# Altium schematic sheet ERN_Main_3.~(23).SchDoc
size A; SheetNumber: 3; SheetTotal: 3; SPICEModelCacheXVWYUVSQ: <root> / <DocumentId>XVWYUVSQ</DocumentId> / <CacheFrame Number="0"> / <Model Name="irf1010" Kind="CKT"> / <Text>*IRF1010 MCE 4-2-96 / *55V  75A .014 ohm HEXFET pkg:TO-220 2,1,3 / .SUBCKT IRF1010  10 20 40 40 / M1   1  2  3  3  DMOS L=1U W=1U / RD  10  1  5.65M / RS  30  3  1.35M / RG  20  2  12.1 / CGS  2  3  2.15N / EGD 12  0  2  1  1 / VFB 14  0  0 / FFB  2  1  VFB  1 / CGD 13 14  4.49N / R1  13  0  1 / D1  12 13  DLIM / DDG 15 14  DCGD / R2  12 15  1 / D2  15  0  DLIM / DSD  3 10  DSUB / LS  30 40  7.5N / .MODEL DMOS NMOS (LEVEL=3 THETA=60M VMAX=114K ETA=2M VTO=3 KP=19.4) / .MODEL DCGD D (CJO=4.49N VJ=.6 M=.68) / .MODEL DSUB D (IS=311N N=1.5 RS=8.67M BV=55 CJO=4.08N VJ=.8 M=.42 TT=100N) / .MODEL DLIM D (IS=100U) / .ENDS IRF1010</Text> / </Model> / <Model Name="1n5400" Kind="MDL"> / <Text>*1N5400 MCE / * 50V 3A Si Rectifier pkg:DO-201 1,2 / .MODEL 1N5400 D(IS=2.68E-12 RS=0.00977 N=1.17 TT=1.44E-5 CJO=1.24E-10 / + VJ=0.6 M=0.333 BV=66.6 IBV=1E-5 )</Text> / </Model> / </CacheFrame> / </root>
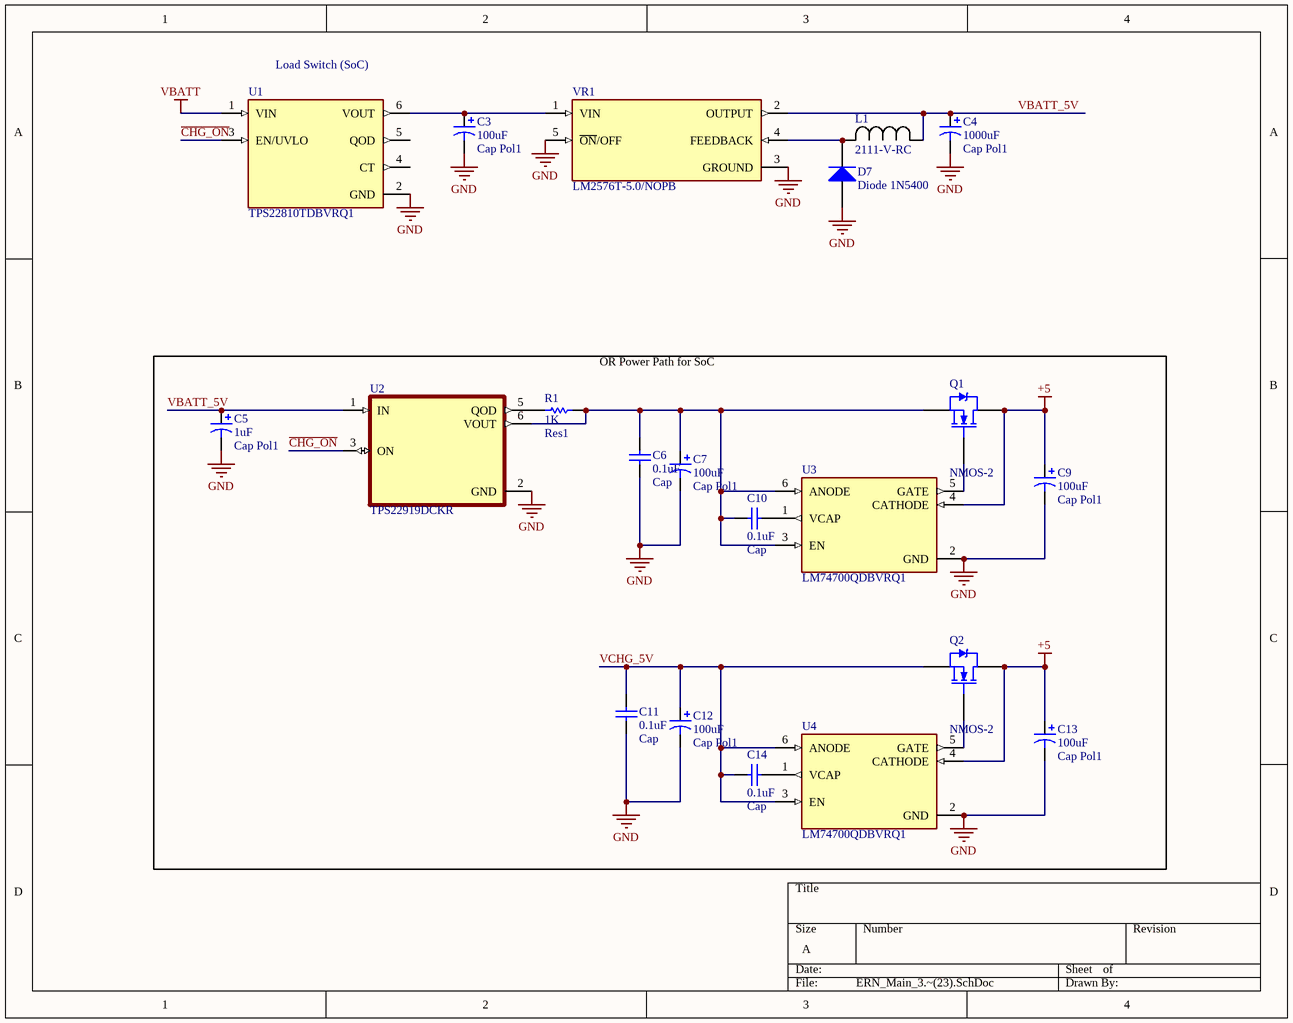
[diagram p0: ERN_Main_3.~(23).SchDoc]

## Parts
C3  Cap Pol1  value 100uF  [RB7.6-15]
C4  Cap Pol1  value 1000uF  [RB7.6-15]
C5  Cap Pol1  value 1uF  [RB7.6-15]
C6  Cap  value 0.1uF  [RAD-0.3]
C7  Cap Pol1  value 100uF  [RB7.6-15]
C9  Cap Pol1  value 100uF  [RB7.6-15]
C10  Cap  value 0.1uF  [RAD-0.3]
C11  Cap  value 0.1uF  [RAD-0.3]
C12  Cap Pol1  value 100uF  [RB7.6-15]
C13  Cap Pol1  value 100uF  [RB7.6-15]
C14  Cap  value 0.1uF  [RAD-0.3]
D7  Diode 1N5400  [DO-201AD]
L1  2111-V-RC  [IND_21XX_27A_V]
Q1  NMOS-2  [TO-220AB]
Q2  NMOS-2  [TO-220AB]
R1  Res1  value 1K  [AXIAL-0.3]
U1  TPS22810TDBVRQ1  [SOT95P280X145-6N]
U2  TPS22919DCKR  [SOT65P210X110-6N]
U3  LM74700QDBVRQ1  [SOT95P280X145-6N]
U4  LM74700QDBVRQ1  [SOT95P280X145-6N]
VR1  LM2576T-5.0/NOPB  [TO170P1067X483X1651-5]

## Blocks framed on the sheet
OR Power Path for SoC: C5-C7 C9-C14 Q1 Q2 R1 U2-U4

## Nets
+5: C9.1 C13.1 Q1.2(D) Q2.2(D) U3.4(CATHODE) U4.4(CATHODE)
GND: C3.2 C4.2 C5.2 C6.1 C7.2 C9.2 C11.1 C12.2 C13.2 D7.1(A) U1.2(GND) U2.2(GND) U3.2(GND) U4.2(GND) VR1.3(GROUND) VR1.5(~{ON}/OFF)
VBATT: U1.1(VIN)
~{CHG_ON}: U1.3(EN/UVLO) U2.3(ON)
VBATT_5V: C4.1 C5.1 L1.1 U2.1(IN) VR1.2(OUTPUT)
VCHG_5V: C11.2 C12.1 C14.2 Q2.3(S) U4.3(EN) U4.6(ANODE)
NetC3_1: C3.1 U1.6(VOUT) VR1.1(VIN)
NetC6_2: C6.2 C7.1 C10.2 Q1.3(S) R1.1 U2.6(VOUT) U3.3(EN) U3.6(ANODE)
NetC10_1: C10.1 U3.1(VCAP)
NetC14_1: C14.1 U4.1(VCAP)
NetD7_2: D7.2(K) L1.2 VR1.4(FEEDBACK)
NetQ1_1: Q1.1(G) U3.5(GATE)
NetQ2_1: Q2.1(G) U4.5(GATE)
NetR1_2: R1.2 U2.5(QOD)

Not connected (* = marked no-connect by the designer): U1 4(CT) 5(QOD)

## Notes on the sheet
- (near U1) Load Switch (SoC)

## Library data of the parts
C3-C5 C7 C9 C12 C13 = Cap Pol1: Polarized Capacitor (Radial)
C6 C10 C11 C14 = Cap: Capacitor
D7 = Diode 1N5400: 3 Amp General Purpose Rectifier
L1 = 2111-V-RC: Inductor 68uH; Manufacturer_Name: Bourns Electronics
Q1 Q2 = NMOS-2: N-Channel Power MOSFET; Note: Pin 2 is electrically connected to pin 4.
R1 = Res1: Resistor
U1 = TPS22810TDBVRQ1: Automotive 1-channel, 18-V, 2-A, 79-mâ„¦ load switch with adj. rise time and adj. output discharge; MF: Texas Instruments
U2 = TPS22919DCKR: 5.5-V, 1.5-A, 90-mÎ© load switch with adj. output discharge; MF: Texas Instruments
U3 U4 = LM74700QDBVRQ1: 3.2-V to 65-V, 80-uA IQ automotive ideal diode controller; MF: Texas Instruments
VR1 = LM2576T-5.0/NOPB: SIMPLE SWITCHERÂ® 40V, 3A Low Component Count Step-Down Regulator; MF: Texas Instruments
